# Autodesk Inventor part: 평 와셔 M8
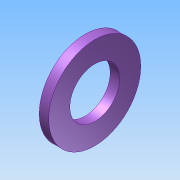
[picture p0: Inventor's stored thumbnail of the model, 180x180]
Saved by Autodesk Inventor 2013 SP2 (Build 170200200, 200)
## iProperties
Created: 2025-07
Part Number: 평 와셔 M8
Material: Generic
Document SubType Name: Modeling
Designer: a
Density: 1 g/cm^3
Author: a
변환 표준: STEP AP214IS
전처리기: Build: 200, Release: 2013 SP2 Update 6 - Date: Thu 07/17/2014
전송 단위: 밀리미터
불확실성: 0.01
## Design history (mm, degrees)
node "평 와셔 M81"
body "Solid1"
node "기준1"
